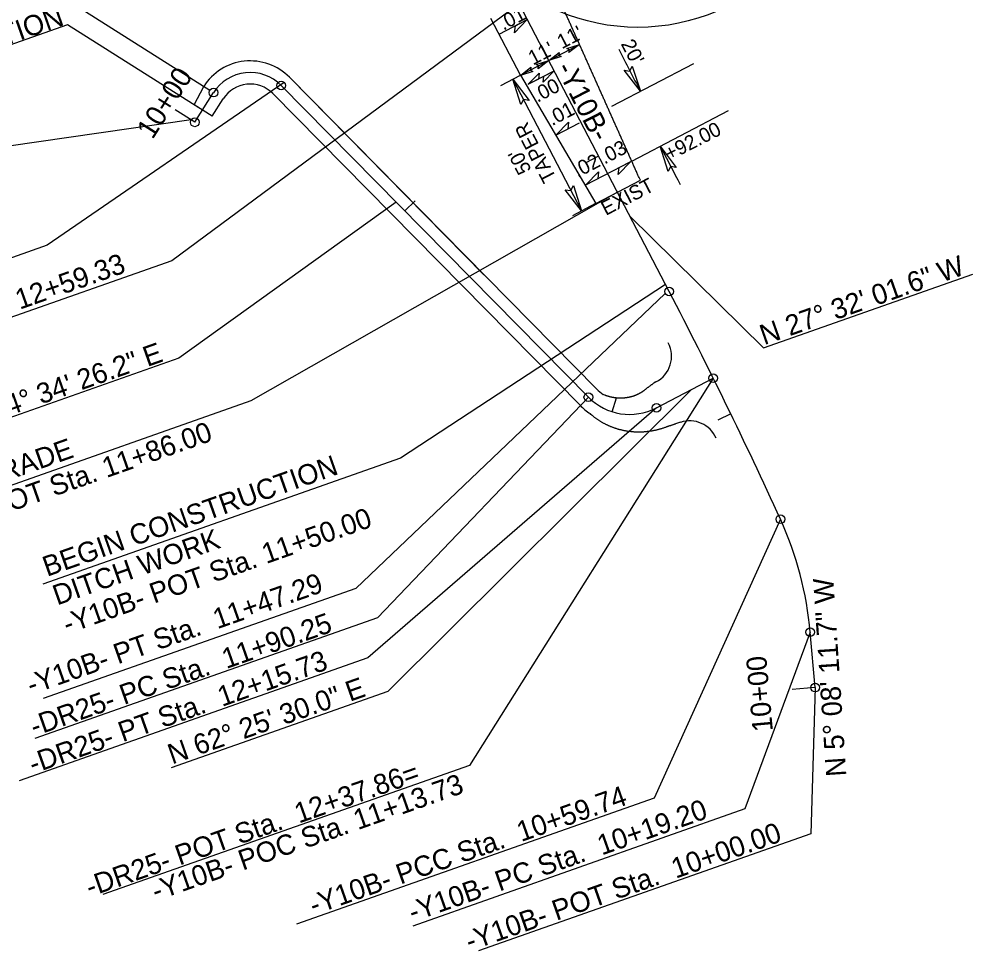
# Model space of a CAD drawing. Extents: x 472216 to 481979, y 489069 to 507339.
# Drawn here: x 475097.2 to 475426.6, y 501650.2 to 501972.1 of the extents above; entities that cross this region are included whole.
import ezdxf

# ---------------------------------------------------------------- set-up
doc = ezdxf.new("R2010")
doc.units = 0
for name, color, linetype in [('Old_Level_12', 7, 'Continuous'), ('Prop Drainage Structure Drop Inlet Grate 2 Narrow Slots and Sag Grates 840 24 CELL', 7, 'Continuous'), ('Prop Drainage Structure Drop Inlet Grate 2 Wide Slots and Sag Grates 840 22 Label', 7, 'Continuous'), ('Prop Drainage Structure Outlet Berm Ditch 850 10 CELL', 7, 'Continuous'), ('Prop Drainage Structure Pipe CSP 15in', 7, 'Continuous'), ('Prop Drainage Structure Pipe RCP 24in Class III Label', 7, 'Continuous'), ('Prop Grid Mask', 7, 'Continuous'), ('Sheet Block Revision CELL', 7, 'Continuous'), ('Sheet North Arrow Point CELL', 7, 'Continuous'), ('Sheet PE Seal Cell', 7, 'Continuous'), ('Sheet Plan And Profile CELL', 7, 'Continuous'), ('Sheet Plot Border Outside CELL', 7, 'Continuous'), ('Sheet Profile Grid Major CELL', 7, 'Continuous'), ('Sheet Profile Grid Minor CELL', 7, 'Continuous')]:
    doc.layers.add(name, color=color, linetype=linetype)

msp = doc.modelspace()

# ---------------------------------------------------------------- linework, layer by layer
at = {"layer": 'Old_Level_12'}
for p, q in [((475163.09, 501947.48), (475106.2, 501983.48)), ((475269.91, 501977.34), (475149.97, 501888.63)), ((475113.99, 501970.13), (474986.13, 501925.05)), ((475159.28, 501941.46), (475113.99, 501970.13)), ((475188.79, 501950.23), (475106.98, 501894)), ((475156.61, 501937.24), (475093.66, 501928.19)), ((475303.81, 501912.31), (475177.25, 501840.27)), ((475227.42, 501908.88), (475152.41, 501854.98)), ((475308.14, 501904), (475354.22, 501858.52)), ((475106.98, 501894), (474994.46, 501854.33)), ((475149.97, 501888.63), (475033.09, 501847.41)), ((475354.22, 501858.52), (475426.58, 501884.04)), ((475320.45, 501880.39), (475228.9, 501820.45)), ((475320.37, 501877.29), (475213.54, 501775.43)), ((475152.41, 501854.98), (475078.23, 501828.82)), ((475336.91, 501848.07), (475252.74, 501714.31)), ((475329.41, 501844.15), (475224.54, 501739.85)), ((475177.25, 501840.27), (475053.77, 501796.73)), ((475293.79, 501841.52), (475221.03, 501765.3)), ((475317.3, 501837.82), (475217.66, 501751.45)), ((475228.9, 501820.45), (475105.42, 501776.91)), ((475360.1, 501799.32), (475316.54, 501702.96)), ((475213.54, 501775.43), (475105.57, 501737.36)), ((475221.03, 501765.3), (475102.73, 501723.59)), ((475370.41, 501760.31), (475347.87, 501699.29)), ((475217.66, 501751.45), (475097.32, 501709.02)), ((475372.13, 501741.18), (475370.66, 501690.68)), ((475224.54, 501739.85), (475149.78, 501713.49)), ((475252.74, 501714.31), (475126.13, 501669.67)), ((475316.54, 501702.96), (475193.07, 501659.42)), ((475347.87, 501699.29), (475233.14, 501658.83)), ((475370.66, 501690.68), (475255.92, 501650.22))]:
    msp.add_line(p, q, dxfattribs=at)
for centre in [(475187.72, 501949.18), (475187.72, 501949.18), (475164.36, 501946.68), (475164.36, 501946.68), (475157.88, 501936.43), (475157.88, 501936.43), (475321.7, 501877.98), (475321.7, 501877.98), (475336.91, 501848.07), (475293.79, 501841.52), (475293.79, 501841.52), (475317.3, 501837.82), (475317.3, 501837.82), (475360.1, 501799.32), (475370.41, 501760.31), (475372.13, 501741.18)]:
    msp.add_circle(centre, 1.5, dxfattribs=at)
at = {"layer": 'Prop Drainage Structure Drop Inlet Grate 2 Narrow Slots and Sag Grates 840 24 CELL'}
for points in [[(475272.72, 501971.94), (475268.32, 501967.4), (475268.62, 501969.81)], [(475273.06, 501949.57), (475276.82, 501953.45), (475276.56, 501951.39)], [(475281.97, 501954.21), (475278.21, 501950.33), (475278.47, 501952.38)], [(475282.57, 501931.97), (475286.97, 501936.52), (475286.67, 501934.11)], [(475308.48, 501922.92), (475304.09, 501918.38), (475304.38, 501920.79)], [(475292.94, 501914.82), (475297.34, 501919.37), (475297.05, 501916.96)]]:
    msp.add_lwpolyline(points, close=True, dxfattribs=at)
at = {"layer": 'Prop Drainage Structure Drop Inlet Grate 2 Wide Slots and Sag Grates 840 22 Label'}
for p, q in [((475262.97, 501966.86), (475272.72, 501971.94)), ((475301.9, 501942.04), (475330.17, 501956.78)), ((475273.06, 501949.57), (475281.97, 501954.21)), ((475308.75, 501923.06), (475342.2, 501940.5)), ((475282.57, 501931.97), (475290.78, 501936.25)), ((475292.94, 501914.82), (475308.48, 501922.92))]:
    msp.add_line(p, q, dxfattribs=at)
for points in [[(475308.92, 501955.85), (475311.8, 501947.19), (475306.11, 501954.41), (475308.07, 501954.15)], [(475321.31, 501919.48), (475318.63, 501928.21), (475324.14, 501920.86), (475322.19, 501921.16)]]:
    msp.add_lwpolyline(points, close=True, dxfattribs=at)
for centre, start in [((476115.78, 502373.47), 206.90539), ((476129.54, 502341.17), 206.98747)]:
    msp.add_arc(centre, 910, start, 207.93192, dxfattribs=at)
at = {"layer": 'Prop Drainage Structure Outlet Berm Ditch 850 10 CELL'}
for points in [[(475286.41, 501961.91), (475290.75, 501963.3), (475287.11, 501960.5), (475287.25, 501961.48)], [(475284.46, 501959.15), (475280.12, 501957.76), (475283.76, 501960.56), (475283.62, 501959.58)], [(475274.67, 501954.04), (475270.32, 501952.65), (475273.96, 501955.45), (475273.82, 501954.47)], [(475275.77, 501956.36), (475280.12, 501957.76), (475276.47, 501954.95), (475276.61, 501955.93)], [(475270.53, 501942.61), (475267.75, 501951.31), (475273.35, 501944.02), (475271.4, 501944.3)], [(475288.65, 501914.56), (475291.44, 501905.86), (475285.84, 501913.15), (475287.79, 501912.87)]]:
    msp.add_lwpolyline(points, close=True, dxfattribs=at)
at = {"layer": 'Prop Drainage Structure Pipe RCP 24in Class III Label'}
for p, q in [((475270.33, 501952.74), (475260.15, 501972.25)), ((475190.57, 501951.99), (475296.64, 501844.32)), ((475190.57, 501951.99), (475296.64, 501844.32)), ((475270.33, 501952.74), (475296.37, 501908.43)), ((475157.72, 501942.45), (475160.98, 501948.81)), ((475157.72, 501942.45), (475160.98, 501948.81)), ((475184.87, 501946.37), (475290.94, 501838.71)), ((475184.87, 501946.37), (475290.94, 501838.71)), ((475163.89, 501938.54), (475157.72, 501942.45)), ((475163.89, 501938.54), (475157.72, 501942.45)), ((475163.89, 501938.54), (475167.74, 501944.54)), ((475163.89, 501938.54), (475167.74, 501944.54)), ((475296.37, 501908.43), (475311.78, 501916.46)), ((475317.15, 501846.77), (475316.49, 501846.43)), ((475317.15, 501846.77), (475316.49, 501846.43)), ((475325.58, 501832.81), (475323.9, 501832.24)), ((475325.58, 501832.81), (475323.9, 501832.24))]:
    msp.add_line(p, q, dxfattribs=at)
for centre, radius, start, end in [((475177.03, 501938.65), 19, 44.574, 147.6705), ((475177.03, 501938.65), 19, 44.574, 147.6705), ((475177.03, 501938.65), 11, 44.574, 147.6705), ((475177.03, 501938.65), 11, 44.574, 147.6705), ((475312.52, 501855.64), 10, 297.575, 27.3501), ((475312.52, 501855.64), 10, 297.575, 27.3501), ((475308.04, 501855.55), 16, 224.574, 235.3093), ((475308.04, 501855.55), 16, 224.574, 235.3093), ((475308.04, 501855.55), 24, 224.574, 235.3093), ((475308.04, 501855.55), 24, 224.574, 235.3093), ((475328.75, 501823.32), 10, 23.4716, 108.4915), ((475328.75, 501823.32), 10, 23.4716, 108.4915)]:
    msp.add_arc(centre, radius, start, end, dxfattribs=at)
for points in [[(475290.75, 501963.3), (475290.48, 501963.92), (475290.2, 501964.54), (475289.93, 501965.16), (475289.65, 501965.77), (475289.37, 501966.39), (475289.1, 501967.01), (475288.82, 501967.63), (475288.54, 501968.24), (475288.27, 501968.86), (475287.99, 501969.48), (475287.71, 501970.1), (475287.44, 501970.72), (475287.16, 501971.33), (475286.89, 501971.95), (475286.61, 501972.57), (475286.33, 501973.19), (475286.06, 501973.81), (475285.78, 501974.42), (475285.5, 501975.04), (475285.23, 501975.66), (475284.95, 501976.28), (475284.67, 501976.9), (475284.4, 501977.51), (475284.12, 501978.13), (475283.85, 501978.75), (475283.57, 501979.37), (475283.29, 501979.98), (475283.02, 501980.6), (475282.74, 501981.22), (475282.46, 501981.84), (475282.19, 501982.46), (475281.91, 501983.07), (475281.64, 501983.67), (475281.4, 501984.23), (475281.17, 501984.8), (475280.94, 501985.36), (475280.72, 501985.93), (475280.5, 501986.5), (475280.29, 501987.07), (475280.09, 501987.64), (475279.9, 501988.22), (475279.71, 501988.79), (475279.52, 501989.37), (475279.34, 501989.95), (475279.17, 501990.53), (475279.01, 501991.11), (475278.85, 501991.7), (475278.7, 501992.28), (475278.55, 501992.87), (475278.41, 501993.46), (475278.28, 501994.04), (475278.15, 501994.63), (475278.04, 501995.22), (475277.92, 501995.81), (475277.82, 501996.41), (475277.72, 501997), (475277.62, 501997.59), (475277.53, 501998.19), (475277.45, 501998.78), (475277.38, 501999.37), (475277.31, 501999.97), (475277.25, 502000.56), (475277.19, 502001.16), (475277.15, 502001.75), (475277.1, 502002.35), (475277.07, 502002.94), (475277.04, 502003.54), (475277.02, 502004.13), (475277, 502004.73), (475276.99, 502005.32), (475276.99, 502005.92), (475276.99, 502006.51), (475277.02, 502007.7)], [(475311.78, 501916.46), (475310.93, 501918.19), (475310.65, 501918.81), (475310.38, 501919.43), (475310.1, 501920.05), (475309.82, 501920.67), (475309.55, 501921.28), (475309.27, 501921.9), (475308.99, 501922.52), (475308.72, 501923.14), (475308.44, 501923.76), (475308.17, 501924.37), (475307.89, 501924.99), (475307.61, 501925.61), (475307.34, 501926.23), (475307.06, 501926.84), (475306.78, 501927.46), (475306.51, 501928.08), (475306.23, 501928.7), (475305.95, 501929.32), (475305.68, 501929.93), (475305.4, 501930.55), (475305.13, 501931.17), (475304.85, 501931.79), (475304.57, 501932.41), (475304.3, 501933.02), (475304.02, 501933.64), (475303.74, 501934.26), (475303.47, 501934.88), (475303.19, 501935.5), (475302.91, 501936.11), (475302.64, 501936.73), (475302.36, 501937.35), (475302.09, 501937.97), (475301.81, 501938.59), (475301.53, 501939.2), (475301.26, 501939.82), (475300.98, 501940.44), (475300.7, 501941.06), (475300.43, 501941.67), (475300.15, 501942.29), (475299.87, 501942.91), (475299.6, 501943.53), (475299.32, 501944.15), (475299.05, 501944.76), (475298.77, 501945.38), (475298.49, 501946), (475298.22, 501946.62), (475297.94, 501947.24), (475297.66, 501947.85), (475297.39, 501948.47), (475297.11, 501949.09), (475296.83, 501949.71), (475296.56, 501950.33), (475296.28, 501950.94), (475296.01, 501951.56), (475295.73, 501952.18), (475295.45, 501952.8), (475295.18, 501953.41), (475294.9, 501954.03), (475294.62, 501954.65), (475294.35, 501955.27), (475294.07, 501955.89), (475293.79, 501956.5), (475293.52, 501957.12), (475293.24, 501957.74), (475292.97, 501958.36), (475292.69, 501958.98), (475292.41, 501959.59), (475292.14, 501960.21), (475291.86, 501960.83), (475291.58, 501961.45), (475291.31, 501962.07), (475291.03, 501962.68), (475290.75, 501963.3)], [(475316.49, 501846.43), (475316.21, 501846.22), (475315.94, 501846.02), (475315.67, 501845.81), (475315.39, 501845.61), (475315.12, 501845.41), (475314.84, 501845.2), (475314.57, 501845), (475314.29, 501844.79), (475314.02, 501844.59), (475313.78, 501844.4), (475313.62, 501844.26), (475313.45, 501844.12), (475313.28, 501843.98), (475313.1, 501843.84), (475312.92, 501843.71), (475312.74, 501843.58), (475312.56, 501843.45), (475312.37, 501843.32), (475312.18, 501843.2), (475311.99, 501843.08), (475311.79, 501842.97), (475311.6, 501842.85), (475311.39, 501842.74), (475311.19, 501842.63), (475310.98, 501842.53), (475310.77, 501842.43), (475310.56, 501842.33), (475310.35, 501842.24), (475310.13, 501842.15), (475309.91, 501842.06), (475309.69, 501841.98), (475309.47, 501841.9), (475309.24, 501841.82), (475309.01, 501841.75), (475308.78, 501841.68), (475308.55, 501841.62), (475308.31, 501841.56), (475308.08, 501841.5), (475307.84, 501841.45), (475307.6, 501841.4), (475307.36, 501841.35), (475307.11, 501841.31), (475306.87, 501841.28), (475306.62, 501841.24), (475306.38, 501841.22), (475306.13, 501841.19), (475305.88, 501841.17), (475305.62, 501841.16), (475305.37, 501841.15), (475305.12, 501841.14), (475304.86, 501841.14), (475304.61, 501841.14), (475304.35, 501841.15), (475304.09, 501841.16), (475303.84, 501841.18), (475303.58, 501841.2), (475303.32, 501841.23), (475303.06, 501841.26), (475302.8, 501841.3), (475302.54, 501841.34), (475302.28, 501841.38), (475302.02, 501841.43), (475301.76, 501841.48), (475301.5, 501841.54), (475301.24, 501841.61), (475300.99, 501841.68), (475300.73, 501841.75), (475300.47, 501841.83), (475300.21, 501841.91), (475299.95, 501842), (475299.7, 501842.09), (475299.44, 501842.19), (475298.93, 501842.4)], [(475316.49, 501846.43), (475316.21, 501846.22), (475315.94, 501846.02), (475315.67, 501845.81), (475315.39, 501845.61), (475315.12, 501845.41), (475314.84, 501845.2), (475314.57, 501845), (475314.29, 501844.79), (475314.02, 501844.59), (475313.78, 501844.4), (475313.62, 501844.26), (475313.45, 501844.12), (475313.28, 501843.98), (475313.1, 501843.84), (475312.92, 501843.71), (475312.74, 501843.58), (475312.56, 501843.45), (475312.37, 501843.32), (475312.18, 501843.2), (475311.99, 501843.08), (475311.79, 501842.97), (475311.6, 501842.85), (475311.39, 501842.74), (475311.19, 501842.63), (475310.98, 501842.53), (475310.77, 501842.43), (475310.56, 501842.33), (475310.35, 501842.24), (475310.13, 501842.15), (475309.91, 501842.06), (475309.69, 501841.98), (475309.47, 501841.9), (475309.24, 501841.82), (475309.01, 501841.75), (475308.78, 501841.68), (475308.55, 501841.62), (475308.31, 501841.56), (475308.08, 501841.5), (475307.84, 501841.45), (475307.6, 501841.4), (475307.36, 501841.35), (475307.11, 501841.31), (475306.87, 501841.28), (475306.62, 501841.24), (475306.38, 501841.22), (475306.13, 501841.19), (475305.88, 501841.17), (475305.62, 501841.16), (475305.37, 501841.15), (475305.12, 501841.14), (475304.86, 501841.14), (475304.61, 501841.14), (475304.35, 501841.15), (475304.09, 501841.16), (475303.84, 501841.18), (475303.58, 501841.2), (475303.32, 501841.23), (475303.06, 501841.26), (475302.8, 501841.3), (475302.54, 501841.34), (475302.28, 501841.38), (475302.02, 501841.43), (475301.76, 501841.48), (475301.5, 501841.54), (475301.24, 501841.61), (475300.99, 501841.68), (475300.73, 501841.75), (475300.47, 501841.83), (475300.21, 501841.91), (475299.95, 501842), (475299.7, 501842.09), (475299.44, 501842.19), (475298.93, 501842.4)], [(475323.9, 501832.24), (475323.57, 501832.14), (475323.25, 501832.03), (475322.92, 501831.92), (475322.6, 501831.81), (475322.27, 501831.7), (475321.95, 501831.59), (475321.62, 501831.49), (475321.3, 501831.38), (475320.98, 501831.27), (475320.61, 501831.14), (475320.18, 501830.98), (475319.74, 501830.83), (475319.29, 501830.68), (475318.85, 501830.55), (475318.41, 501830.42), (475317.96, 501830.3), (475317.51, 501830.18), (475317.07, 501830.08), (475316.62, 501829.98), (475316.17, 501829.89), (475315.72, 501829.81), (475315.27, 501829.73), (475314.82, 501829.67), (475314.36, 501829.61), (475313.91, 501829.56), (475313.46, 501829.52), (475313.01, 501829.48), (475312.56, 501829.45), (475312.11, 501829.44), (475311.66, 501829.42), (475311.21, 501829.42), (475310.77, 501829.42), (475310.32, 501829.44), (475309.88, 501829.45), (475309.43, 501829.48), (475308.99, 501829.52), (475308.55, 501829.56), (475308.11, 501829.61), (475307.67, 501829.66), (475307.24, 501829.73), (475306.8, 501829.8), (475306.37, 501829.88), (475305.94, 501829.96), (475305.52, 501830.06), (475305.09, 501830.16), (475304.67, 501830.26), (475304.25, 501830.38), (475303.84, 501830.5), (475303.42, 501830.63), (475303.01, 501830.76), (475302.61, 501830.9), (475302.2, 501831.05), (475301.8, 501831.2), (475301.41, 501831.36), (475301.02, 501831.53), (475300.63, 501831.71), (475300.24, 501831.89), (475299.86, 501832.07), (475299.48, 501832.26), (475299.11, 501832.46), (475298.74, 501832.67), (475298.38, 501832.88), (475298.02, 501833.09), (475297.66, 501833.31), (475297.31, 501833.54), (475296.97, 501833.77), (475296.63, 501834.01), (475296.29, 501834.25), (475295.96, 501834.5), (475295.63, 501834.76), (475295.31, 501835.01), (475295, 501835.28), (475294.38, 501835.82)], [(475323.9, 501832.24), (475323.57, 501832.14), (475323.25, 501832.03), (475322.92, 501831.92), (475322.6, 501831.81), (475322.27, 501831.7), (475321.95, 501831.59), (475321.62, 501831.49), (475321.3, 501831.38), (475320.98, 501831.27), (475320.61, 501831.14), (475320.18, 501830.98), (475319.74, 501830.83), (475319.29, 501830.68), (475318.85, 501830.55), (475318.41, 501830.42), (475317.96, 501830.3), (475317.51, 501830.18), (475317.07, 501830.08), (475316.62, 501829.98), (475316.17, 501829.89), (475315.72, 501829.81), (475315.27, 501829.73), (475314.82, 501829.67), (475314.36, 501829.61), (475313.91, 501829.56), (475313.46, 501829.52), (475313.01, 501829.48), (475312.56, 501829.45), (475312.11, 501829.44), (475311.66, 501829.42), (475311.21, 501829.42), (475310.77, 501829.42), (475310.32, 501829.44), (475309.88, 501829.45), (475309.43, 501829.48), (475308.99, 501829.52), (475308.55, 501829.56), (475308.11, 501829.61), (475307.67, 501829.66), (475307.24, 501829.73), (475306.8, 501829.8), (475306.37, 501829.88), (475305.94, 501829.96), (475305.52, 501830.06), (475305.09, 501830.16), (475304.67, 501830.26), (475304.25, 501830.38), (475303.84, 501830.5), (475303.42, 501830.63), (475303.01, 501830.76), (475302.61, 501830.9), (475302.2, 501831.05), (475301.8, 501831.2), (475301.41, 501831.36), (475301.02, 501831.53), (475300.63, 501831.71), (475300.24, 501831.89), (475299.86, 501832.07), (475299.48, 501832.26), (475299.11, 501832.46), (475298.74, 501832.67), (475298.38, 501832.88), (475298.02, 501833.09), (475297.66, 501833.31), (475297.31, 501833.54), (475296.97, 501833.77), (475296.63, 501834.01), (475296.29, 501834.25), (475295.96, 501834.5), (475295.63, 501834.76), (475295.31, 501835.01), (475295, 501835.28), (475294.38, 501835.82)]]:
    msp.add_spline(points, degree=3, dxfattribs=at)
at = {"layer": 'Prop Grid Mask'}
msp.add_line((475190.57, 501951.99), (475257.74, 501883.81), dxfattribs=at)
msp.add_line((475190.57, 501951.99), (475257.74, 501883.81), dxfattribs=at)
msp.add_arc((475177.03, 501938.65), 19, 44.574, 147.6705, dxfattribs=at)
msp.add_arc((475177.03, 501938.65), 19, 44.574, 147.6705, dxfattribs=at)
at = {"layer": 'Sheet Block Revision CELL'}
for p, q in [((475270.36, 501952.67), (475290.75, 501963.3)), ((475263.54, 501949.11), (475270.36, 501952.67)), ((475267.75, 501951.31), (475291.44, 501905.86)), ((475288.44, 501904.3), (475296.43, 501908.46))]:
    msp.add_line(p, q, dxfattribs=at)
at = {"layer": 'Sheet North Arrow Point CELL'}
for p, q in [((475321.7, 501877.98), (475269.91, 501977.34)), ((475187.72, 501949.18), (475293.79, 501841.52)), ((475187.72, 501949.18), (475293.79, 501841.52)), ((475157.88, 501936.43), (475164.36, 501946.68)), ((475157.88, 501936.43), (475164.36, 501946.68)), ((475317.3, 501837.82), (475336.91, 501848.07)), ((475317.3, 501837.82), (475336.91, 501848.07)), ((475372.13, 501741.18), (475370.41, 501760.31))]:
    msp.add_line(p, q, dxfattribs=at)
for centre, radius, start, end in [((475177.03, 501938.65), 15, 44.574, 147.6705), ((475177.03, 501938.65), 15, 44.574, 147.6705), ((473858.59, 501115.23), 1650, 24.49379, 27.53379), ((475308.04, 501855.55), 20, 224.574, 297.575), ((475308.04, 501855.55), 20, 224.574, 297.575), ((475250.89, 501749.56), 120, 5.1366, 24.4938)]:
    msp.add_arc(centre, radius, start, end, dxfattribs=at)
at = {"layer": 'Sheet PE Seal Cell'}
for p, q in [((475297.34, 501924.72), (475292.9, 501922.41)), ((475230.45, 501905.81), (475234.01, 501909.32)), ((475230.45, 501905.81), (475234.01, 501909.32)), ((475302.03, 501836.48), (475303.53, 501841.25)), ((475302.03, 501836.48), (475303.53, 501841.25)), ((475342.96, 501835.74), (475338.46, 501833.56))]:
    msp.add_line(p, q, dxfattribs=at)
at = {"layer": 'Sheet Plot Border Outside CELL'}
msp.add_circle((475310.9, 502038.88), 69.64, dxfattribs=at)
at = {"layer": 'Sheet Profile Grid Minor CELL'}
for p, q in [((475157.88, 501936.43), (475151.12, 501940.71)), ((475157.88, 501936.43), (475151.12, 501940.71)), ((475372.13, 501741.18), (475364.16, 501740.47))]:
    msp.add_line(p, q, dxfattribs=at)

# ---------------------------------------------------------------- texts
at = {"layer": 'Old_Level_12'}
for s, rotation, p in [('BEGIN CONSTRUCTION', 19.3241, (475012.11, 501934.72)), ('-Y10B- PC Sta.  12+59.33', 19.423, (475032.19, 501848.67)), ('-Y10B- POT Sta. 11+86.00', 19.423, (475058.73, 501789.34)), ('BEGIN GRADE', 19.423, (475055.24, 501799.24)), ('BEGIN CONSTRUCTION', 19.423, (475106.89, 501779.42)), ('-Y10B- POT Sta. 11+50.00', 19.423, (475113.87, 501759.62)), ('DITCH WORK', 19.423, (475110.38, 501769.52)), ('-Y10B- PT Sta.  11+47.29', 19.423, (475101.41, 501738.66)), ('-DR25- PC Sta.  11+90.25', 19.3711, (475102.53, 501724.29)), ('-DR25- PT Sta.  12+15.73', 19.5584, (475102.12, 501711.33)), ('-DR25- POT Sta.  12+37.86=', 19.3866, (475121.71, 501668.81)), ('-Y10B- POC Sta. 11+13.73', 19.3866, (475144.51, 501667.42)), ('-Y10B- PCC Sta.  10+59.74', 19.423, (475198.97, 501662.56)), ('-Y10B- PC Sta.  10+19.20', 19.423, (475233.15, 501660.16)), ('-Y10B- POT Sta.  10+00.00', 19.423, (475252.83, 501650.07))]:
    msp.add_text(s, height=7, rotation=rotation, dxfattribs=at).set_placement(p)
at = {"layer": 'Prop Drainage Structure Drop Inlet Grate 2 Narrow Slots and Sag Grates 840 24 CELL'}
for s, p in [('.01', (475264.45, 501968.05)), ('.00', (475276.22, 501943.19)), ('.01', (475281.3, 501935.12)), ('.03', (475299.37, 501921.82)), ('.02', (475290.11, 501917.16)), ('EXIST', (475299.83, 501904.09))]:
    msp.add_text(s, height=5, rotation=27.5338, dxfattribs=at).set_placement(p)
at = {"layer": 'Prop Drainage Structure Drop Inlet Grate 2 Wide Slots and Sag Grates 840 22 Label'}
for s, rotation, p in [("20'", 297.499, (475304.89, 501963.53)), ('+92.00', 26.9117, (475321.74, 501923.05))]:
    msp.add_text(s, height=5, rotation=rotation, dxfattribs=at).set_placement(p)
at = {"layer": 'Prop Drainage Structure Pipe CSP 15in'}
for s, rotation, p in [("11'", 27.5338, (475284.65, 501961.63)), ("11'", 27.5338, (475274.68, 501956.07)), ('TAPER', 117.5338, (475282.87, 501917.23)), ("50'", 117.5338, (475274.27, 501920.02))]:
    msp.add_text(s, height=5, rotation=rotation, dxfattribs=at).set_placement(p)
at = {"layer": 'Sheet Plan And Profile CELL'}
for s, rotation, p in [('-Y10B-', 297.0425, (475282.5, 501955.22)), ('N 27%%d 32\' 01.6" W', 19.423, (475354.48, 501859.43)), ('S 44%%d 34\' 26.2" E', 19.423, (475080.64, 501830.44)), ('N 5%%d 08\' 11.7" W', 93.7857, (475382.89, 501710.65)), ('N 62%%d 25\' 30.0" E', 19.423, (475150.09, 501714.61))]:
    msp.add_text(s, height=7, rotation=rotation, dxfattribs=at).set_placement(p)
at = {"layer": 'Sheet Profile Grid Major CELL'}
for rotation, p in [(57.6705, (475143.32, 501930.26)), (57.6705, (475143.32, 501930.26)), (95.1366, (475357.53, 501726.21))]:
    msp.add_text('10+00', height=7, rotation=rotation, dxfattribs=at).set_placement(p)

doc.saveas('drawing.dxf')
